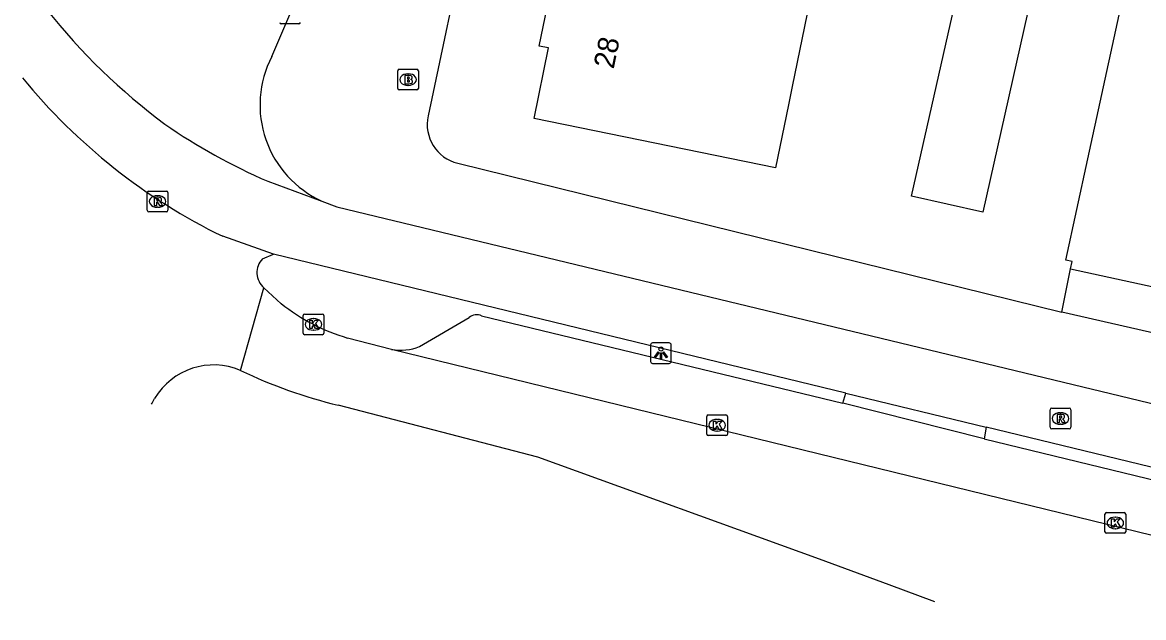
# Model space of a CAD drawing. Extents: x 160037 to 160839, y 385326 to 386441.
# Drawn here: x 160583.4 to 160637.6, y 385352.9 to 385381.6 of the extents above; entities that cross this region are included whole.
import ezdxf

# ---------------------------------------------------------------- set-up
doc = ezdxf.new("R2010")
doc.units = 0
for name, color, linetype in [('IMGEO_Brandkraan', 7, 'Continuous'), ('IMGEO_Fietspad_gesloten', 7, 'Continuous'), ('IMGEO_Kolk', 7, 'Continuous'), ('IMGEO_Lichtpunt', 7, 'Continuous'), ('IMGEO_Pand', 7, 'Continuous'), ('IMGEO_Pand_nummerreeks', 7, 'Continuous'), ('IMGEO_Parkeervlak_open', 7, 'Continuous'), ('IMGEO_Rijbaan_lokaal_gesloten', 7, 'Continuous'), ('IMGEO_Rioolput', 7, 'Continuous'), ('IMGEO_Voetpad_open', 7, 'Continuous')]:
    doc.layers.add(name, color=color, linetype=linetype)

msp = doc.modelspace()

# ---------------------------------------------------------------- linework, layer by layer
at = {"layer": 'IMGEO_Brandkraan'}
for p, q in [((160601.584, 385378.425), (160601.584, 385379.277)), ((160601.659, 385379.351), (160602.511, 385379.351)), ((160602.585, 385379.277), (160602.585, 385378.425)), ((160602.072, 385379.131), (160602.097, 385379.131)), ((160602.511, 385378.351), (160601.659, 385378.351)), ((160602.095, 385378.571), (160602.07, 385378.571))]:
    msp.add_line(p, q, dxfattribs=at)
for points in [[(160601.584, 385378.425), (160601.584, 385379.277)], [(160601.659, 385379.351), (160602.511, 385379.351)], [(160602.585, 385379.277), (160602.585, 385378.425)], [(160601.932, 385379.051), (160601.932, 385378.651), (160602.145, 385378.651)], [(160602.163, 385379.051), (160601.932, 385379.051)], [(160602.111, 385378.97), (160602.057, 385378.97), (160602.057, 385378.894)], [(160602.057, 385378.894), (160602.11, 385378.894)], [(160602.119, 385378.818), (160602.057, 385378.818), (160602.057, 385378.737)], [(160602.057, 385378.737), (160602.119, 385378.737)], [(160602.511, 385378.351), (160601.659, 385378.351)]]:
    msp.add_lwpolyline(points, dxfattribs=at)
for centre, radius, start, end in [((160601.661, 385379.275), 0.0765, 91.552, 178.448), ((160601.661, 385379.275), 0.0765, 91.552, 178.448), ((160602.509, 385379.275), 0.0765, 1.552, 88.448), ((160602.509, 385379.275), 0.0765, 1.552, 88.448), ((160602.112, 385378.932), 0.0379, 267.8285, 90.9355), ((160602.12, 385378.777), 0.0404, 269.8759, 90.5077), ((160602.151, 385378.902), 0.251, 268.6676, 293.5347), ((160602.167, 385378.906), 0.145, 59.4692, 91.5367), ((160602.192, 385378.953), 0.0922, 285.5137, 58.1501), ((160602.197, 385378.761), 0.105, 301.3115, 78.989), ((160601.661, 385378.427), 0.0765, 181.552, 268.448), ((160601.661, 385378.427), 0.0765, 181.552, 268.448), ((160602.509, 385378.427), 0.0765, 271.552, 358.448), ((160602.509, 385378.427), 0.0765, 271.552, 358.448)]:
    msp.add_arc(centre, radius, start, end, dxfattribs=at)
for centre, major_axis, ratio, start_param, end_param in [((160602.071, 385378.851), (-0.387, 0.002), 0.722429, 4.712389, 7.853982), ((160602.096, 385378.851), (-0.39, 0.002), 0.717154, 1.570796, 4.712389)]:
    msp.add_ellipse(centre, major_axis=major_axis, ratio=ratio, start_param=start_param, end_param=end_param, dxfattribs=at)
at = {"layer": 'IMGEO_Fietspad_gesloten'}
for points in [[(160595.304, 385373.937), (160597.917, 385372.977)], [(160597.917, 385372.977), (160598.642, 385372.71), (160665.613, 385356.547)], [(160623.238, 385363.704), (160595.58, 385370.409)], [(160623.238, 385363.704), (160630.031, 385362.057)], [(160659.2, 385354.983), (160630.031, 385362.057)]]:
    msp.add_lwpolyline(points, dxfattribs=at)
for centre, radius, start, end in [((160608.363, 385401.032), 30.284, 218.3481, 233.4535), ((160606.434, 385399.807), 28.163, 235.1226, 246.7213)]:
    msp.add_arc(centre, radius, start, end, dxfattribs=at)
at = {"layer": 'IMGEO_Kolk'}
for p, q in [((160596.806, 385381.541), (160595.954, 385381.541)), ((160597.012, 385366.595), (160597.012, 385367.447)), ((160597.087, 385367.521), (160597.939, 385367.521)), ((160597.5, 385367.301), (160597.525, 385367.301)), ((160598.013, 385367.447), (160598.013, 385366.595)), ((160597.523, 385366.741), (160597.498, 385366.741)), ((160597.939, 385366.521), (160597.087, 385366.521)), ((160616.523, 385361.721), (160616.523, 385362.573)), ((160616.598, 385362.647), (160617.45, 385362.647)), ((160617.011, 385362.427), (160617.036, 385362.427)), ((160617.524, 385362.573), (160617.524, 385361.721)), ((160617.034, 385361.867), (160617.009, 385361.867)), ((160617.45, 385361.647), (160616.598, 385361.647)), ((160635.77, 385356.998), (160635.77, 385357.85)), ((160635.845, 385357.924), (160636.697, 385357.924)), ((160636.258, 385357.704), (160636.283, 385357.704)), ((160636.771, 385357.85), (160636.771, 385356.998)), ((160636.281, 385357.144), (160636.256, 385357.144)), ((160636.697, 385356.924), (160635.845, 385356.924))]:
    msp.add_line(p, q, dxfattribs=at)
for points in [[(160596.806, 385381.541), (160595.954, 385381.541)], [(160597.012, 385366.595), (160597.012, 385367.447)], [(160597.087, 385367.521), (160597.939, 385367.521)], [(160598.013, 385367.447), (160598.013, 385366.595)], [(160597.333, 385367.221), (160597.456, 385367.221), (160597.456, 385367.07), (160597.586, 385367.221), (160597.75, 385367.221), (160597.604, 385367.07), (160597.757, 385366.821), (160597.605, 385366.821), (160597.52, 385366.985), (160597.456, 385366.918), (160597.456, 385366.821), (160597.333, 385366.821), (160597.333, 385367.221)], [(160597.939, 385366.521), (160597.087, 385366.521)], [(160616.523, 385361.721), (160616.523, 385362.573)], [(160616.598, 385362.647), (160617.45, 385362.647)], [(160617.524, 385362.573), (160617.524, 385361.721)], [(160616.844, 385362.347), (160616.967, 385362.347), (160616.967, 385362.196), (160617.097, 385362.347), (160617.261, 385362.347), (160617.115, 385362.196), (160617.268, 385361.947), (160617.116, 385361.947), (160617.031, 385362.111), (160616.967, 385362.044), (160616.967, 385361.947), (160616.844, 385361.947), (160616.844, 385362.347)], [(160617.45, 385361.647), (160616.598, 385361.647)], [(160635.77, 385356.998), (160635.77, 385357.85)], [(160635.845, 385357.924), (160636.697, 385357.924)], [(160636.091, 385357.624), (160636.214, 385357.624), (160636.214, 385357.473), (160636.344, 385357.624), (160636.508, 385357.624), (160636.362, 385357.473), (160636.515, 385357.224), (160636.363, 385357.224), (160636.278, 385357.388), (160636.214, 385357.321), (160636.214, 385357.224), (160636.091, 385357.224), (160636.091, 385357.624)], [(160636.771, 385357.85), (160636.771, 385356.998)], [(160636.697, 385356.924), (160635.845, 385356.924)]]:
    msp.add_lwpolyline(points, dxfattribs=at)
for centre, start, end in [((160595.956, 385381.617), 181.552, 268.448), ((160595.956, 385381.617), 181.552, 268.448), ((160596.804, 385381.617), 271.552, 358.448), ((160596.804, 385381.617), 271.552, 358.448), ((160597.089, 385367.445), 91.552, 178.448), ((160597.089, 385367.445), 91.552, 178.448), ((160597.937, 385367.445), 1.552, 88.448), ((160597.937, 385367.445), 1.552, 88.448), ((160597.089, 385366.597), 181.552, 268.448), ((160597.089, 385366.597), 181.552, 268.448), ((160597.937, 385366.597), 271.552, 358.448), ((160597.937, 385366.597), 271.552, 358.448), ((160616.6, 385362.571), 91.552, 178.448), ((160616.6, 385362.571), 91.552, 178.448), ((160617.448, 385362.571), 1.552, 88.448), ((160617.448, 385362.571), 1.552, 88.448), ((160616.6, 385361.723), 181.552, 268.448), ((160616.6, 385361.723), 181.552, 268.448), ((160617.448, 385361.723), 271.552, 358.448), ((160617.448, 385361.723), 271.552, 358.448), ((160635.847, 385357.848), 91.552, 178.448), ((160635.847, 385357.848), 91.552, 178.448), ((160636.695, 385357.848), 1.552, 88.448), ((160636.695, 385357.848), 1.552, 88.448), ((160635.847, 385357), 181.552, 268.448), ((160635.847, 385357), 181.552, 268.448), ((160636.695, 385357), 271.552, 358.448), ((160636.695, 385357), 271.552, 358.448)]:
    msp.add_arc(centre, 0.0765, start, end, dxfattribs=at)
for centre, major_axis, ratio, start_param, end_param in [((160597.499, 385367.021), (-0.387, 0.002), 0.722429, 4.712389, 7.853982), ((160597.524, 385367.021), (-0.39, 0.002), 0.717154, 1.570796, 4.712389), ((160617.01, 385362.147), (-0.387, 0.002), 0.722429, 4.712389, 7.853982), ((160617.035, 385362.147), (-0.39, 0.002), 0.717154, 1.570796, 4.712389), ((160636.257, 385357.424), (-0.387, 0.002), 0.722429, 4.712389, 7.853982), ((160636.282, 385357.424), (-0.39, 0.002), 0.717154, 1.570796, 4.712389)]:
    msp.add_ellipse(centre, major_axis=major_axis, ratio=ratio, start_param=start_param, end_param=end_param, dxfattribs=at)
at = {"layer": 'IMGEO_Lichtpunt'}
for p, q in [((160613.806, 385366.033), (160613.806, 385365.226)), ((160613.806, 385366.033), (160613.806, 385365.226)), ((160614.708, 385366.128), (160613.9, 385366.128)), ((160614.708, 385366.128), (160613.9, 385366.128)), ((160614.802, 385365.226), (160614.802, 385366.033)), ((160614.802, 385365.226), (160614.802, 385366.033)), ((160613.9, 385365.132), (160614.708, 385365.132)), ((160613.9, 385365.132), (160614.708, 385365.132))]:
    msp.add_line(p, q, dxfattribs=at)
for points in [[(160614.18, 385365.697), (160614.219, 385365.669), (160614.031, 385365.407), (160613.993, 385365.434), (160614.18, 385365.697)], [(160614.282, 385365.649), (160614.329, 385365.649), (160614.329, 385365.327), (160614.282, 385365.327), (160614.282, 385365.649)], [(160614.392, 385365.669), (160614.43, 385365.696), (160614.617, 385365.434), (160614.578, 385365.406), (160614.392, 385365.669)]]:
    msp.add_lwpolyline(points, dxfattribs=at)
msp.add_circle((160614.305, 385365.831), 0.0994, dxfattribs=at)
for centre, start, end in [((160613.9, 385366.033), 90, 180), ((160613.9, 385366.033), 90, 180), ((160614.708, 385366.033), 0, 90), ((160614.708, 385366.033), 0, 90), ((160613.9, 385365.226), 180, 270), ((160613.9, 385365.226), 180, 270), ((160614.708, 385365.226), 270, 0), ((160614.708, 385365.226), 270, 360)]:
    msp.add_arc(centre, 0.0946, start, end, dxfattribs=at)
at = {"layer": 'IMGEO_Pand'}
for points in [[(160634.107, 385369.703), (160634.186, 385370.064), (160633.885, 385370.129), (160634.947, 385375.015), (160639.764, 385397.18), (160640.008, 385397.127), (160640.084, 385397.476), (160661.597, 385392.801)], [(160619.536, 385382.998), (160621.492, 385382.597), (160620.657, 385378.521), (160620.476, 385377.635), (160619.85, 385374.58), (160608.181, 385376.97), (160608.88, 385380.381), (160608.422, 385380.475), (160609.172, 385384.139), (160609.69, 385384.033), (160609.884, 385384.977)], [(160632.386, 385383.662), (160629.864, 385372.447), (160626.426, 385373.22), (160628.948, 385384.436), (160632.386, 385383.662)], [(160634.107, 385369.703), (160656.042, 385364.936), (160656.102, 385365.216), (160656.326, 385365.167), (160657.453, 385370.355), (160667.916, 385368.081), (160667.98, 385368.379), (160668.318, 385368.305), (160669.587, 385374.144)]]:
    msp.add_lwpolyline(points, dxfattribs=at)
at = {"layer": 'IMGEO_Parkeervlak_open'}
for points in [[(160602.642, 385365.956), (160605.03, 385367.352)], [(160605.639, 385367.435), (160623.098, 385363.21)], [(160629.931, 385361.491), (160651.296, 385356.305)]]:
    msp.add_lwpolyline(points, dxfattribs=at)
for centre, radius, start, end in [((160605.404, 385366.88), 0.602, 67.086, 128.436), ((160601.731, 385368.123), 2.351, 259.1742, 292.8086)]:
    msp.add_arc(centre, radius, start, end, dxfattribs=at)
at = {"layer": 'IMGEO_Rijbaan_lokaal_gesloten'}
for points in [[(160595.58, 385370.409), (160593.125, 385371.277)], [(160595.043, 385370.188), (160595.58, 385370.409)], [(160593.989, 385364.799), (160595.118, 385368.791)], [(160595.949, 385368.022), (160595.118, 385368.791)], [(160601.289, 385365.814), (160599.163, 385366.36)], [(160654.267, 385352.851), (160601.289, 385365.814)], [(160589.689, 385363.171), (160589.708, 385363.209), (160589.829, 385363.446)], [(160627.54, 385353.61), (160625.34, 385354.429), (160621.979, 385355.681), (160608.349, 385360.608), (160598.713, 385363.114)]]:
    msp.add_lwpolyline(points, dxfattribs=at)
for centre, radius, start, end in [((160605.758, 385397.189), 28.827, 219.2772, 244.009), ((160595.742, 385369.525), 0.963, 136.5148, 229.6313), ((160601.917, 385375.624), 9.664, 231.8666, 253.4452), ((160592.691, 385361.717), 3.344, 67.169, 148.8643), ((160604.068, 385385.592), 23.107, 244.1387, 256.5998)]:
    msp.add_arc(centre, radius, start, end, dxfattribs=at)
at = {"layer": 'IMGEO_Rioolput'}
for p, q in [((160589.477, 385372.536), (160589.477, 385373.388)), ((160589.552, 385373.462), (160590.404, 385373.462)), ((160589.965, 385373.242), (160589.99, 385373.242)), ((160590.478, 385373.388), (160590.478, 385372.536)), ((160590.404, 385372.462), (160589.552, 385372.462)), ((160589.988, 385372.682), (160589.963, 385372.682)), ((160633.194, 385362.973), (160634.046, 385362.973)), ((160633.119, 385362.047), (160633.119, 385362.899)), ((160633.607, 385362.753), (160633.632, 385362.753)), ((160634.12, 385362.899), (160634.12, 385362.047)), ((160634.046, 385361.973), (160633.194, 385361.973)), ((160633.63, 385362.193), (160633.605, 385362.193))]:
    msp.add_line(p, q, dxfattribs=at)
for points in [[(160589.477, 385372.536), (160589.477, 385373.388)], [(160589.552, 385373.462), (160590.404, 385373.462)], [(160590.478, 385373.388), (160590.478, 385372.536)], [(160590.066, 385373.16), (160589.814, 385373.162), (160589.814, 385372.762)], [(160589.814, 385372.762), (160589.938, 385372.762), (160589.938, 385372.924), (160589.949, 385372.924)], [(160589.992, 385373.081), (160589.938, 385373.081), (160589.938, 385373)], [(160589.938, 385373), (160589.99, 385373)], [(160589.996, 385372.895), (160590.067, 385372.762), (160590.207, 385372.762), (160590.142, 385372.888)], [(160590.404, 385372.462), (160589.552, 385372.462)], [(160633.194, 385362.973), (160634.046, 385362.973)], [(160633.119, 385362.047), (160633.119, 385362.899)], [(160633.708, 385362.671), (160633.456, 385362.673), (160633.456, 385362.273)], [(160633.456, 385362.273), (160633.58, 385362.273), (160633.58, 385362.435), (160633.591, 385362.435)], [(160633.634, 385362.592), (160633.58, 385362.592), (160633.58, 385362.511)], [(160633.58, 385362.511), (160633.632, 385362.511)], [(160633.638, 385362.406), (160633.709, 385362.273), (160633.849, 385362.273), (160633.784, 385362.399)], [(160634.12, 385362.899), (160634.12, 385362.047)], [(160634.046, 385361.973), (160633.194, 385361.973)]]:
    msp.add_lwpolyline(points, dxfattribs=at)
for centre, radius, start, end in [((160589.554, 385373.386), 0.0765, 91.552, 178.448), ((160589.554, 385373.386), 0.0765, 91.552, 178.448), ((160590.402, 385373.386), 0.0765, 1.552, 88.448), ((160590.402, 385373.386), 0.0765, 1.552, 88.448), ((160589.948, 385372.871), 0.0533, 26.0293, 88.6989), ((160589.974, 385373.189), 0.19, 274.7715, 282.9687), ((160589.998, 385372.985), 0.0964, 77.0061, 93.1865), ((160590.012, 385373.042), 0.0378, 276.6634, 79.6772), ((160590.065, 385373.05), 0.109, 350.3612, 89.416), ((160590.063, 385373.05), 0.112, 277.5842, 350.9817), ((160590.047, 385372.835), 0.108, 29.5134, 73.7905), ((160589.554, 385372.538), 0.0765, 181.552, 268.448), ((160589.554, 385372.538), 0.0765, 181.552, 268.448), ((160590.402, 385372.538), 0.0765, 271.552, 358.448), ((160590.402, 385372.538), 0.0765, 271.552, 358.448), ((160633.196, 385362.897), 0.0765, 91.552, 178.448), ((160633.196, 385362.897), 0.0765, 91.552, 178.448), ((160634.044, 385362.897), 0.0765, 1.552, 88.448), ((160634.044, 385362.897), 0.0765, 1.552, 88.448), ((160633.59, 385362.382), 0.0533, 26.0293, 88.6989), ((160633.616, 385362.7), 0.19, 274.7715, 282.9687), ((160633.64, 385362.496), 0.0964, 77.0061, 93.1865), ((160633.654, 385362.553), 0.0378, 276.6634, 79.6772), ((160633.707, 385362.561), 0.109, 350.3612, 89.416), ((160633.705, 385362.561), 0.112, 277.5842, 350.9817), ((160633.689, 385362.346), 0.108, 29.5134, 73.7905), ((160633.196, 385362.049), 0.0765, 181.552, 268.448), ((160633.196, 385362.049), 0.0765, 181.552, 268.448), ((160634.044, 385362.049), 0.0765, 271.552, 358.448), ((160634.044, 385362.049), 0.0765, 271.552, 358.448)]:
    msp.add_arc(centre, radius, start, end, dxfattribs=at)
for centre, major_axis, ratio, start_param, end_param in [((160589.964, 385372.962), (-0.387, 0.002), 0.722429, 4.712389, 7.853982), ((160589.989, 385372.962), (-0.39, 0.002), 0.717154, 1.570796, 4.712389), ((160633.606, 385362.473), (-0.387, 0.002), 0.722429, 4.712389, 7.853982), ((160633.631, 385362.473), (-0.39, 0.002), 0.717154, 1.570796, 4.712389)]:
    msp.add_ellipse(centre, major_axis=major_axis, ratio=ratio, start_param=start_param, end_param=end_param, dxfattribs=at)
at = {"layer": 'IMGEO_Voetpad_open'}
for points in [[(160608.712, 385403.89), (160603.051, 385377.093)], [(160595.493, 385379.966), (160597.619, 385384.944), (160598.689, 385387.36), (160601.869, 385394.874)], [(160604.484, 385374.806), (160633.69, 385367.617)], [(160633.69, 385367.617), (160634.107, 385369.703)], [(160660.235, 385361.55), (160633.69, 385367.617)], [(160623.098, 385363.21), (160623.238, 385363.704)], [(160629.931, 385361.491), (160623.098, 385363.21)], [(160630.031, 385362.057), (160629.931, 385361.491)]]:
    msp.add_lwpolyline(points, dxfattribs=at)
for centre, radius, start, end in [((160600.035, 385377.626), 5.109, 152.7462, 245.51), ((160604.946, 385376.688), 1.938, 167.9388, 256.2025)]:
    msp.add_arc(centre, radius, start, end, dxfattribs=at)

# ---------------------------------------------------------------- texts
at = {"layer": 'IMGEO_Pand_nummerreeks'}
msp.add_text('28', height=1, rotation=78.3348, dxfattribs=at).set_placement((160612.019, 385379.335))

doc.saveas('drawing.dxf')
